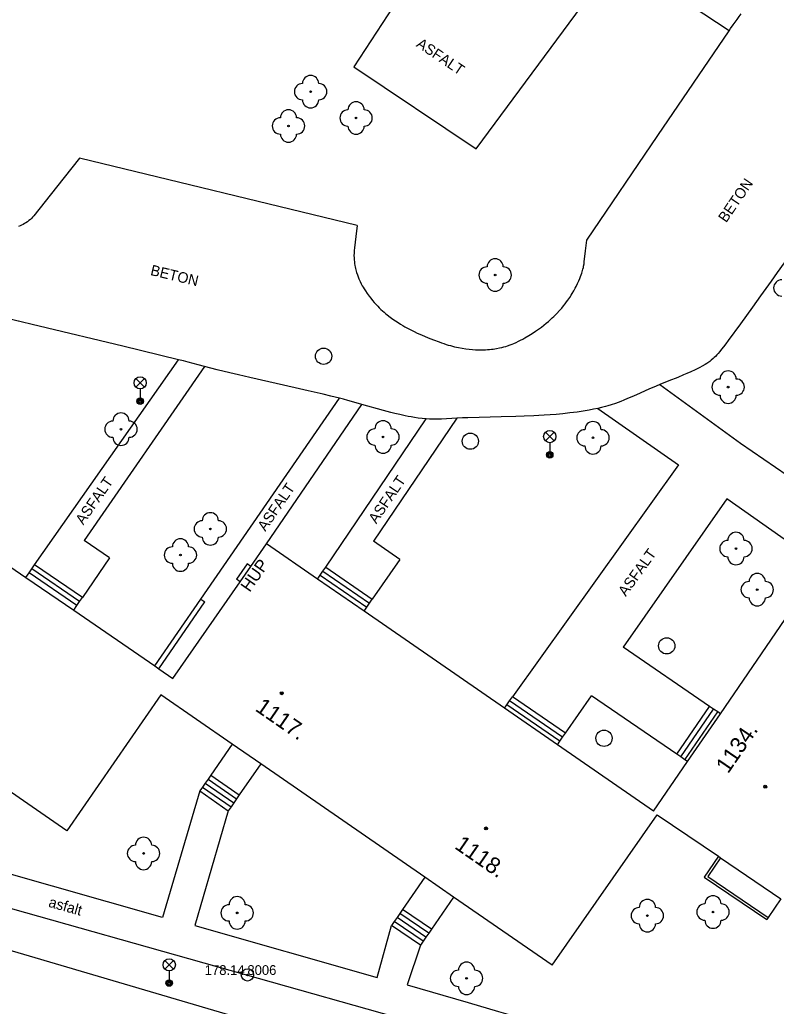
# Model space of a CAD drawing. Extents: x -539515 to -538098, y -1182060 to -1180157.
# Drawn here: x -538763.3 to -538716.8, y -1181224.5 to -1181163.7 of the extents above; entities that cross this region are included whole.
import ezdxf

# ---------------------------------------------------------------- set-up
doc = ezdxf.new("R2010")
doc.units = 0
for name, color, linetype in [('Vrstva 10', 7, 'Continuous'), ('Vrstva 11', 7, 'Continuous'), ('Vrstva 21', 7, 'Continuous'), ('Vrstva 22', 7, 'Continuous'), ('Vrstva 23', 7, 'Continuous'), ('Vrstva 24', 7, 'Continuous'), ('Vrstva 27', 7, 'Continuous'), ('Vrstva 33', 7, 'Continuous'), ('Vrstva 39', 7, 'Continuous'), ('Vrstva 40', 7, 'Continuous'), ('Vrstva 41', 7, 'Continuous'), ('Vrstva 47', 7, 'Continuous'), ('Vrstva 5', 7, 'Continuous'), ('Vrstva 7', 7, 'Continuous')]:
    doc.layers.add(name, color=color, linetype=linetype)

msp = doc.modelspace()

# ---------------------------------------------------------------- linework, layer by layer
at = {"layer": 'Vrstva 10'}
for p, q in [((-538724.04, -1181170.835), (-538719.66, -1181164.39)), ((-538728.42, -1181177.28), (-538724.04, -1181170.835)), ((-538742.55, -1181176.37), (-538759.65, -1181172.24)), ((-538756.982, -1181183.814), (-538762.131, -1181182.578)), ((-538753.55, -1181184.64), (-538756.982, -1181183.814))]:
    msp.add_line(p, q, dxfattribs=at)
for points in [[(-538719.66, -1181164.39), (-538719.568, -1181164.257), (-538719.404, -1181164.028), (-538719.154, -1181163.686), (-538719.031, -1181163.514), (-538718.91, -1181163.34)], [(-538759.65, -1181172.24), (-538761.055, -1181174.01), (-538762.46, -1181175.78), (-538762.5, -1181175.829), (-538762.542, -1181175.876), (-538762.583, -1181175.92), (-538762.67, -1181176.003), (-538762.758, -1181176.079), (-538762.848, -1181176.146), (-538762.938, -1181176.208), (-538763.029, -1181176.263), (-538763.121, -1181176.312), (-538763.211, -1181176.357), (-538763.302, -1181176.397), (-538763.391, -1181176.433)], [(-538742.55, -1181176.37), (-538742.635, -1181177.058), (-538742.72, -1181177.747), (-538742.737, -1181177.917), (-538742.747, -1181178.076), (-538742.749, -1181178.225), (-538742.746, -1181178.363), (-538742.738, -1181178.493), (-538742.727, -1181178.615), (-538742.712, -1181178.728), (-538742.695, -1181178.834), (-538742.676, -1181178.934), (-538742.656, -1181179.027), (-538742.635, -1181179.114), (-538742.589, -1181179.277), (-538742.542, -1181179.42), (-538742.496, -1181179.544), (-538742.452, -1181179.653), (-538742.41, -1181179.748), (-538742.371, -1181179.831), (-538742.299, -1181179.976), (-538742.24, -1181180.084), (-538742.193, -1181180.166), (-538742.119, -1181180.288), (-538742.04, -1181180.41), (-538741.929, -1181180.571), (-538741.819, -1181180.722), (-538741.711, -1181180.863), (-538741.603, -1181180.995), (-538741.497, -1181181.119), (-538741.393, -1181181.235), (-538741.29, -1181181.344), (-538741.189, -1181181.446), (-538741.09, -1181181.542), (-538740.992, -1181181.633), (-538740.896, -1181181.718), (-538740.803, -1181181.799), (-538740.711, -1181181.875), (-538740.531, -1181182.016), (-538740.359, -1181182.143), (-538740.195, -1181182.257), (-538740.039, -1181182.359), (-538739.891, -1181182.452), (-538739.751, -1181182.535), (-538739.618, -1181182.611), (-538739.493, -1181182.681), (-538739.255, -1181182.805), (-538739.044, -1181182.91), (-538738.857, -1181182.998), (-538738.692, -1181183.072), (-538738.401, -1181183.198), (-538738.181, -1181183.289), (-538737.847, -1181183.421), (-538737.51, -1181183.55), (-538737.365, -1181183.603)], [(-538714.704, -1181176.313), (-538715.01, -1181176.79), (-538715.29, -1181177.216), (-538715.555, -1181177.613), (-538715.805, -1181177.984), (-538716.28, -1181178.675), (-538716.699, -1181179.277), (-538717.069, -1181179.802), (-538717.722, -1181180.717), (-538718.216, -1181181.401), (-538718.962, -1181182.425), (-538719.71, -1181183.45), (-538719.864, -1181183.66), (-538720, -1181183.843), (-538720.122, -1181184.001), (-538720.233, -1181184.137), (-538720.332, -1181184.253), (-538720.421, -1181184.352), (-538720.502, -1181184.436)], [(-538730.446, -1181181.975), (-538730.35, -1181181.88), (-538730.262, -1181181.79), (-538730.102, -1181181.617), (-538729.965, -1181181.461), (-538729.849, -1181181.321), (-538729.75, -1181181.195), (-538729.666, -1181181.083), (-538729.593, -1181180.984), (-538729.47, -1181180.805), (-538729.381, -1181180.668), (-538729.316, -1181180.564), (-538729.221, -1181180.404), (-538729.13, -1181180.24), (-538729.077, -1181180.14), (-538728.983, -1181179.953), (-538728.908, -1181179.79), (-538728.847, -1181179.646), (-538728.797, -1181179.52), (-538728.757, -1181179.409), (-538728.725, -1181179.312), (-538728.699, -1181179.227), (-538728.658, -1181179.076), (-538728.631, -1181178.962), (-538728.613, -1181178.875), (-538728.591, -1181178.745), (-538728.573, -1181178.613), (-538728.496, -1181177.946), (-538728.42, -1181177.28)], [(-538762.131, -1181182.578), (-538764.706, -1181181.96), (-538767.28, -1181181.34), (-538768.045, -1181181.155), (-538768.81, -1181180.97), (-538769.744, -1181180.745), (-538771.146, -1181180.414), (-538771.848, -1181180.251)], [(-538737.365, -1181183.603), (-538737.223, -1181183.652), (-538737.084, -1181183.696), (-538736.949, -1181183.737), (-538736.816, -1181183.775), (-538736.686, -1181183.809), (-538736.56, -1181183.84), (-538736.437, -1181183.868), (-538736.317, -1181183.894), (-538736.084, -1181183.937), (-538735.864, -1181183.971), (-538735.656, -1181183.996), (-538735.461, -1181184.015), (-538735.278, -1181184.027), (-538735.106, -1181184.033), (-538734.945, -1181184.035), (-538734.794, -1181184.033), (-538734.653, -1181184.028), (-538734.521, -1181184.02), (-538734.398, -1181184.009), (-538734.283, -1181183.997), (-538734.175, -1181183.984), (-538733.974, -1181183.953), (-538733.8, -1181183.92), (-538733.649, -1181183.885), (-538733.517, -1181183.852), (-538733.403, -1181183.819), (-538733.304, -1181183.788), (-538733.132, -1181183.729), (-538733.004, -1181183.68), (-538732.909, -1181183.641), (-538732.769, -1181183.578), (-538732.63, -1181183.51), (-538732.493, -1181183.439), (-538732.362, -1181183.368), (-538732.236, -1181183.298), (-538731.997, -1181183.158), (-538731.776, -1181183.021), (-538731.574, -1181182.888), (-538731.388, -1181182.758), (-538731.217, -1181182.633), (-538731.061, -1181182.513), (-538730.916, -1181182.396), (-538730.784, -1181182.284), (-538730.662, -1181182.176), (-538730.549, -1181182.073), (-538730.446, -1181181.975)], [(-538745.564, -1181186.55), (-538746.363, -1181186.367), (-538749.161, -1181185.737), (-538749.86, -1181185.577), (-538750.384, -1181185.454), (-538751.168, -1181185.266), (-538751.559, -1181185.169), (-538751.95, -1181185.07), (-538752.35, -1181184.963), (-538752.949, -1181184.797), (-538753.249, -1181184.716), (-538753.55, -1181184.64)], [(-538720.502, -1181184.436), (-538720.574, -1181184.508), (-538720.639, -1181184.569), (-538720.756, -1181184.671), (-538720.847, -1181184.744), (-538720.918, -1181184.796)], [(-538720.918, -1181184.796), (-538721.027, -1181184.871), (-538721.14, -1181184.94), (-538721.308, -1181185.034), (-538721.467, -1181185.119), (-538721.617, -1181185.195), (-538721.758, -1181185.265), (-538722.024, -1181185.39), (-538722.258, -1181185.494), (-538722.464, -1181185.582), (-538722.826, -1181185.732), (-538723.372, -1181185.95), (-538723.92, -1181186.17), (-538724.157, -1181186.269), (-538724.598, -1181186.461), (-538725.366, -1181186.804), (-538725.654, -1181186.931), (-538725.907, -1181187.039), (-538726.13, -1181187.13)], [(-538744.652, -1181186.764), (-538745.564, -1181186.55)], [(-538735.732, -1181188.213), (-538736.071, -1181188.226), (-538736.41, -1181188.24), (-538737.361, -1181188.296), (-538737.598, -1181188.305), (-538737.776, -1181188.308), (-538737.91, -1181188.308), (-538738.11, -1181188.303), (-538738.31, -1181188.29), (-538738.562, -1181188.265), (-538738.798, -1181188.236), (-538739.018, -1181188.204), (-538739.224, -1181188.169), (-538739.416, -1181188.134), (-538739.596, -1181188.098), (-538739.933, -1181188.025), (-538740.227, -1181187.956), (-538740.483, -1181187.891), (-538740.931, -1181187.773), (-538742.27, -1181187.4), (-538742.615, -1181187.302), (-538743.132, -1181187.151), (-538743.39, -1181187.079), (-538743.65, -1181187.01), (-538744.167, -1181186.882), (-538744.652, -1181186.764)], [(-538726.13, -1181187.13), (-538726.326, -1181187.207), (-538726.498, -1181187.273), (-538726.65, -1181187.328), (-538726.917, -1181187.418), (-538727.12, -1181187.481), (-538727.273, -1181187.525), (-538727.505, -1181187.586), (-538727.74, -1181187.64), (-538728.009, -1181187.695), (-538728.27, -1181187.744), (-538728.523, -1181187.788), (-538728.769, -1181187.827), (-538729.007, -1181187.862), (-538729.237, -1181187.894), (-538729.46, -1181187.922), (-538729.893, -1181187.971), (-538730.3, -1181188.009), (-538730.681, -1181188.04), (-538731.038, -1181188.065), (-538731.373, -1181188.085), (-538731.688, -1181188.101), (-538732.278, -1181188.126), (-538732.794, -1181188.142), (-538733.698, -1181188.164), (-538735.054, -1181188.194), (-538735.732, -1181188.213)]]:
    msp.add_lwpolyline(points, dxfattribs=at)
at = {"layer": 'Vrstva 11'}
for p, q in [((-538736.25, -1181156.58), (-538742.75, -1181166.61)), ((-538735.22, -1181171.66), (-538726.507, -1181159.859)), ((-538719.66, -1181164.39), (-538726.507, -1181159.859)), ((-538742.75, -1181166.61), (-538735.22, -1181171.66)), ((-538762.41, -1181197.27), (-538753.55, -1181184.64)), ((-538751.95, -1181185.07), (-538759.36, -1181195.77)), ((-538723.92, -1181186.17), (-538718.96, -1181189.79)), ((-538752.18, -1181199.39), (-538743.65, -1181187.01)), ((-538748.13, -1181195.98), (-538742.27, -1181187.4)), ((-538727.74, -1181187.64), (-538722.78, -1181191.12)), ((-538744.49, -1181197.41), (-538738.31, -1181188.29)), ((-538736.41, -1181188.24), (-538741.55, -1181195.81)), ((-538718.96, -1181189.79), (-538712.702, -1181194.072)), ((-538722.78, -1181191.12), (-538733, -1181205.39)), ((-538719.81, -1181193.21), (-538726.19, -1181202.34)), ((-538714.61, -1181196.86), (-538719.81, -1181193.21)), ((-538757.793, -1181196.844), (-538759.36, -1181195.77)), ((-538739.923, -1181196.934), (-538741.55, -1181195.81)), ((-538759.467, -1181199.287), (-538762.41, -1181197.27)), ((-538757.793, -1181196.844), (-538759.467, -1181199.287)), ((-538744.49, -1181197.41), (-538741.62, -1181199.39)), ((-538739.923, -1181196.934), (-538741.62, -1181199.39)), ((-538759.806, -1181199.781), (-538762.749, -1181197.764)), ((-538759.636, -1181199.534), (-538762.579, -1181197.517)), ((-538744.83, -1181197.901), (-538741.961, -1181199.883)), ((-538744.659, -1181197.654), (-538741.79, -1181199.636)), ((-538720.86, -1181205.988), (-538726.19, -1181202.34)), ((-538730.078, -1181208.136), (-538733.34, -1181205.883)), ((-538729.908, -1181207.889), (-538733.17, -1181205.636)), ((-538729.738, -1181207.643), (-538733, -1181205.39)), ((-538729.738, -1181207.643), (-538728.14, -1181205.33)), ((-538722.875, -1181208.933), (-538728.14, -1181205.33)), ((-538722.875, -1181208.933), (-538720.86, -1181205.988)), ((-538722.627, -1181209.102), (-538720.612, -1181206.157)), ((-538722.379, -1181209.271), (-538720.364, -1181206.326)), ((-538751.901, -1181210.715), (-538750.148, -1181211.926)), ((-538751.731, -1181210.468), (-538749.978, -1181211.679)), ((-538751.56, -1181210.221), (-538749.807, -1181211.432)), ((-538752.23, -1181211.19), (-538754.53, -1181218.99)), ((-538752.23, -1181211.19), (-538750.49, -1181212.42)), ((-538752.072, -1181210.962), (-538750.319, -1181212.173)), ((-538750.49, -1181212.42), (-538752.55, -1181219.47)), ((-538754.53, -1181218.99), (-538769.32, -1181214.77)), ((-538733.22, -1181227.08), (-538775.4, -1181215.19)), ((-538716.472, -1181217.831), (-538717.255, -1181218.985)), ((-538737.982, -1181219.708), (-538739.758, -1181218.482)), ((-538738.493, -1181220.449), (-538740.269, -1181219.223)), ((-538738.323, -1181220.202), (-538740.099, -1181218.976)), ((-538738.152, -1181219.955), (-538739.928, -1181218.729)), ((-538752.55, -1181219.47), (-538741.32, -1181222.67)), ((-538741.32, -1181222.67), (-538740.44, -1181219.47)), ((-538738.66, -1181220.69), (-538740.44, -1181219.47)), ((-538738.66, -1181220.69), (-538739.48, -1181223.14))]:
    msp.add_line(p, q, dxfattribs=at)
for points in [[(-538762.945, -1181198.05), (-538762.749, -1181197.764), (-538762.579, -1181197.517), (-538762.41, -1181197.27)], [(-538744.997, -1181198.144), (-538744.83, -1181197.901), (-538744.659, -1181197.654), (-538744.49, -1181197.41)], [(-538760.002, -1181200.068), (-538759.806, -1181199.781), (-538759.636, -1181199.534), (-538759.467, -1181199.287)], [(-538742.129, -1181200.126), (-538741.961, -1181199.883), (-538741.79, -1181199.636), (-538741.62, -1181199.39)], [(-538733.488, -1181206.096), (-538733.34, -1181205.883), (-538733.17, -1181205.636), (-538733, -1181205.39)], [(-538720.2, -1181206.44), (-538720.364, -1181206.326), (-538720.612, -1181206.157), (-538720.86, -1181205.988)], [(-538730.226, -1181208.35), (-538730.078, -1181208.136), (-538729.908, -1181207.889), (-538729.738, -1181207.643)], [(-538750.245, -1181208.316), (-538751.56, -1181210.221), (-538751.731, -1181210.468), (-538751.901, -1181210.715), (-538752.072, -1181210.962), (-538752.23, -1181211.19)], [(-538722.215, -1181209.385), (-538722.379, -1181209.271), (-538722.627, -1181209.102), (-538722.875, -1181208.933)], [(-538748.492, -1181209.527), (-538749.807, -1181211.432), (-538749.978, -1181211.679), (-538750.148, -1181211.926), (-538750.319, -1181212.173), (-538750.49, -1181212.42)], [(-538738.391, -1181216.504), (-538739.758, -1181218.482), (-538739.928, -1181218.729), (-538740.099, -1181218.976), (-538740.269, -1181219.223), (-538740.44, -1181219.47)], [(-538736.616, -1181217.73), (-538737.982, -1181219.708), (-538738.152, -1181219.955), (-538738.323, -1181220.202), (-538738.493, -1181220.449), (-538738.66, -1181220.69)], [(-538739.48, -1181223.14), (-538735.731, -1181224.223), (-538733.856, -1181224.764), (-538731.98, -1181225.3)]]:
    msp.add_lwpolyline(points, dxfattribs=at)
at = {"layer": 'Vrstva 21'}
for radius in [0.375, 0.375, 0.05, 0.05]:
    msp.add_circle((-538749.31, -1181222.52), radius, dxfattribs=at)
at = {"layer": 'Vrstva 22'}
for centre in [(-538745.42, -1181168.14), (-538742.62, -1181169.76), (-538746.78, -1181170.25), (-538734.06, -1181179.43), (-538719.72, -1181186.33), (-538757.09, -1181188.92), (-538740.96, -1181189.4), (-538728.04, -1181189.45), (-538751.59, -1181195.06), (-538753.43, -1181196.67), (-538719.24, -1181196.27), (-538717.93, -1181198.8), (-538755.7, -1181215.04), (-538749.94, -1181218.7), (-538720.65, -1181218.65), (-538724.69, -1181218.87), (-538735.82, -1181222.73)]:
    msp.add_circle(centre, 0.05, dxfattribs=at)
for centre, start, end in [((-538745.92, -1181168.14), 90, 270), ((-538745.42, -1181167.64), 0, 180), ((-538744.92, -1181168.14), 270, 90), ((-538745.42, -1181168.64), 180, 0), ((-538742.62, -1181169.26), 0, 180), ((-538746.78, -1181169.75), 0, 180), ((-538743.12, -1181169.76), 90, 270), ((-538742.12, -1181169.76), 270, 90), ((-538747.28, -1181170.25), 90, 270), ((-538746.28, -1181170.25), 270, 90), ((-538742.62, -1181170.26), 180, 0), ((-538746.78, -1181170.75), 180, 0), ((-538734.06, -1181178.93), 0, 180), ((-538734.56, -1181179.43), 90, 270), ((-538733.56, -1181179.43), 270, 90), ((-538716.42, -1181180.22), 90, 270), ((-538734.06, -1181179.93), 180, 0), ((-538720.22, -1181186.33), 90, 270), ((-538719.72, -1181185.83), 0, 180), ((-538719.22, -1181186.33), 270, 90), ((-538719.72, -1181186.83), 180, 0), ((-538757.09, -1181188.42), 0, 180), ((-538757.59, -1181188.92), 90, 270), ((-538756.59, -1181188.92), 270, 90), ((-538741.46, -1181189.4), 90, 270), ((-538740.96, -1181188.9), 0, 180), ((-538740.46, -1181189.4), 270, 90), ((-538728.04, -1181188.95), 0, 180), ((-538757.09, -1181189.42), 180, 0), ((-538728.54, -1181189.45), 90, 270), ((-538727.54, -1181189.45), 270, 90), ((-538740.96, -1181189.9), 180, 0), ((-538728.04, -1181189.95), 180, 0), ((-538751.59, -1181194.56), 0, 180), ((-538752.09, -1181195.06), 90, 270), ((-538751.09, -1181195.06), 270, 90), ((-538751.59, -1181195.56), 180, 0), ((-538719.24, -1181195.77), 0, 180), ((-538753.93, -1181196.67), 90, 270), ((-538753.43, -1181196.17), 0, 180), ((-538752.93, -1181196.67), 270, 90), ((-538719.74, -1181196.27), 90, 270), ((-538718.74, -1181196.27), 270, 90), ((-538719.24, -1181196.77), 180, 0), ((-538753.43, -1181197.17), 180, 0), ((-538717.93, -1181198.3), 0, 180), ((-538718.43, -1181198.8), 90, 270), ((-538717.43, -1181198.8), 270, 90), ((-538717.93, -1181199.3), 180, 0), ((-538755.7, -1181214.54), 0, 180), ((-538756.2, -1181215.04), 90, 270), ((-538755.2, -1181215.04), 270, 90), ((-538755.7, -1181215.54), 180, 0), ((-538749.94, -1181218.2), 0, 180), ((-538724.69, -1181218.37), 0, 180), ((-538720.65, -1181218.15), 0, 180), ((-538750.44, -1181218.7), 90, 270), ((-538749.44, -1181218.7), 270, 90), ((-538725.19, -1181218.87), 90, 270), ((-538724.19, -1181218.87), 270, 90), ((-538721.15, -1181218.65), 90, 270), ((-538720.15, -1181218.65), 270, 90), ((-538749.94, -1181219.2), 180, 0), ((-538720.65, -1181219.15), 180, 0), ((-538724.69, -1181219.37), 180, 0), ((-538736.32, -1181222.73), 90, 270), ((-538735.82, -1181222.23), 0, 180), ((-538735.32, -1181222.73), 270, 90), ((-538735.82, -1181223.23), 180, 0)]:
    msp.add_arc(centre, 0.5, start, end, dxfattribs=at)
at = {"layer": 'Vrstva 24'}
for p, q in [((-538749.333, -1181197.205), (-538749.99, -1181198.15)), ((-538749.097, -1181197.369), (-538749.333, -1181197.205)), ((-538749.754, -1181198.314), (-538749.99, -1181198.15))]:
    msp.add_line(p, q, dxfattribs=at)
at = {"layer": 'Vrstva 27'}
for centre in [(-538744.62, -1181184.43), (-538735.59, -1181189.66), (-538723.5, -1181202.26), (-538727.36, -1181207.95)]:
    msp.add_circle(centre, 0.5, dxfattribs=at)
at = {"layer": 'Vrstva 33'}
for p, q in [((-538756.175, -1181186.33), (-538755.645, -1181185.8)), ((-538756.175, -1181185.8), (-538755.645, -1181186.33)), ((-538755.91, -1181186.44), (-538755.91, -1181187.19)), ((-538730.965, -1181189.64), (-538730.435, -1181189.11)), ((-538730.965, -1181189.11), (-538730.435, -1181189.64)), ((-538730.7, -1181189.75), (-538730.7, -1181190.5)), ((-538754.385, -1181222.16), (-538753.855, -1181221.63)), ((-538754.385, -1181221.63), (-538753.855, -1181222.16)), ((-538754.12, -1181222.27), (-538754.12, -1181223.02))]:
    msp.add_line(p, q, dxfattribs=at)
for centre, radius in [((-538755.91, -1181186.065), 0.375), ((-538755.91, -1181187.19), 0.2), ((-538755.91, -1181187.19), 0.145), ((-538755.91, -1181187.19), 0.0876), ((-538730.7, -1181189.375), 0.375), ((-538730.7, -1181190.5), 0.2), ((-538730.7, -1181190.5), 0.145), ((-538730.7, -1181190.5), 0.0876), ((-538754.12, -1181221.895), 0.375), ((-538754.12, -1181223.02), 0.2), ((-538754.12, -1181223.02), 0.145), ((-538754.12, -1181223.02), 0.0876)]:
    msp.add_circle(centre, radius, dxfattribs=at)
at = {"layer": 'Vrstva 39'}
for centre, radius in [((-538747.195, -1181205.18), 0.09), ((-538747.195, -1181205.18), 0.0398), ((-538717.437, -1181210.93), 0.09), ((-538717.437, -1181210.93), 0.0398), ((-538734.62, -1181213.497), 0.09), ((-538734.62, -1181213.497), 0.0398)]:
    msp.add_circle(centre, radius, dxfattribs=at)
at = {"layer": 'Vrstva 5'}
for p, q in [((-538754.64, -1181205.28), (-538760.42, -1181213.64)), ((-538730.55, -1181221.92), (-538724.09, -1181212.66))]:
    msp.add_line(p, q, dxfattribs=at)
for points in [[(-538771.831, -1181191.955), (-538762.945, -1181198.05)], [(-538749.097, -1181197.369), (-538748.13, -1181195.98)], [(-538744.997, -1181198.144), (-538748.13, -1181195.98)], [(-538749.754, -1181198.314), (-538749.097, -1181197.369)], [(-538720.2, -1181206.44), (-538713.952, -1181197.311)], [(-538762.945, -1181198.05), (-538760.002, -1181200.068)], [(-538753.89, -1181204.26), (-538749.754, -1181198.314)], [(-538742.129, -1181200.126), (-538744.997, -1181198.144)], [(-538760.002, -1181200.068), (-538754.999, -1181203.5)], [(-538733.488, -1181206.096), (-538742.129, -1181200.126)], [(-538754.999, -1181203.5), (-538754.751, -1181203.669)], [(-538754.751, -1181203.669), (-538753.89, -1181204.26)], [(-538750.245, -1181208.316), (-538754.64, -1181205.28)], [(-538730.226, -1181208.35), (-538733.488, -1181206.096)], [(-538722.215, -1181209.385), (-538720.2, -1181206.44)], [(-538748.492, -1181209.527), (-538750.245, -1181208.316)], [(-538724.306, -1181212.44), (-538730.226, -1181208.35)], [(-538760.42, -1181213.64), (-538766.517, -1181209.445)], [(-538738.391, -1181216.504), (-538748.492, -1181209.527)], [(-538724.306, -1181212.44), (-538722.215, -1181209.385)], [(-538724.09, -1181212.66), (-538720.321, -1181215.218)], [(-538720.321, -1181215.218), (-538720.196, -1181215.302)], [(-538720.196, -1181215.302), (-538716.472, -1181217.831)], [(-538736.616, -1181217.73), (-538738.391, -1181216.504)], [(-538730.55, -1181221.92), (-538736.616, -1181217.73)]]:
    msp.add_lwpolyline(points, dxfattribs=at)
at = {"layer": 'Vrstva 7'}
for p, q in [((-538754.751, -1181203.669), (-538751.932, -1181199.559)), ((-538720.321, -1181215.218), (-538721.189, -1181216.496)), ((-538720.196, -1181215.302), (-538720.979, -1181216.456)), ((-538721.189, -1181216.496), (-538717.34, -1181219.11)), ((-538770.69, -1181219.01), (-538735.9, -1181229.24))]:
    msp.add_line(p, q, dxfattribs=at)
for points in [[(-538754.999, -1181203.5), (-538752.18, -1181199.39), (-538751.932, -1181199.559)], [(-538720.979, -1181216.456), (-538717.255, -1181218.985), (-538717.34, -1181219.11)]]:
    msp.add_lwpolyline(points, dxfattribs=at)

# ---------------------------------------------------------------- texts
at = {"layer": 'Vrstva 22'}
msp.add_text('178.14 ', height=0.6, dxfattribs=at).set_placement((-538751.937, -1181222.52))
at = {"layer": 'Vrstva 23'}
msp.add_text('8006', height=0.6, dxfattribs=at).set_placement((-538749.31, -1181222.52))
at = {"layer": 'Vrstva 40'}
for s, rotation, p in [('ASFALT', 326.15219, (-538738.962, -1181165.328)), ('BETON', 55.71646, (-538719.84, -1181176.244)), ('BETON', 346.42192, (-538755.321, -1181179.419)), ('ASFALT', 55.29649, (-538759.408, -1181194.852)), ('ASFALT', 55.82365, (-538741.373, -1181194.784)), ('ASFALT', 55.66756, (-538748.203, -1181195.25)), ('ASFALT', 54.39022, (-538726.017, -1181199.257)), ('asfalt', 344.25754, (-538761.594, -1181218.313))]:
    msp.add_text(s, height=0.65, rotation=rotation, dxfattribs=at).set_placement(p)
at = {"layer": 'Vrstva 41'}
msp.add_text('HUP', height=0.75, rotation=55.1915, dxfattribs=at).set_placement((-538749.169, -1181198.997))
at = {"layer": 'Vrstva 47'}
for s, rotation, p in [('1117.', 325.36549, (-538748.885, -1181206.217)), ('1134.', 55.61267, (-538719.725, -1181210.175)), ('1118.', 325.36549, (-538736.612, -1181214.695))]:
    msp.add_text(s, height=1, rotation=rotation, dxfattribs=at).set_placement(p)

doc.saveas('drawing.dxf')
